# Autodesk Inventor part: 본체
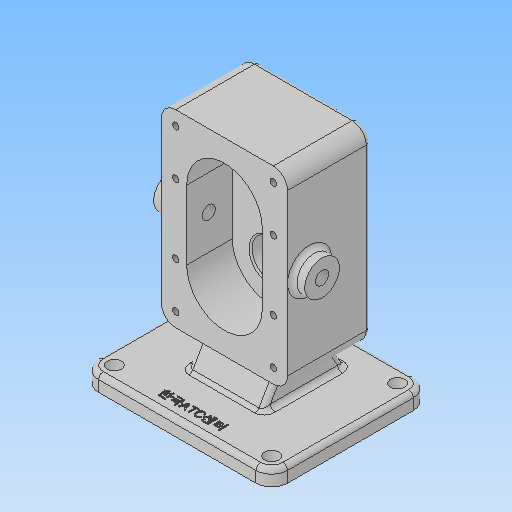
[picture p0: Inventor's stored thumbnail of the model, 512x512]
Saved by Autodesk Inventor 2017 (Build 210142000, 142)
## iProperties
Part Number: 본체
Material: 일반
Document SubType Name: Modeling
Designer: MRC
Density: 1 g/cm^3
Appearance: 기본값
Mass: 546.121 g
Surface Area: 823.386 cm^2
Volume: 546.121 cm^3
Author: MRC
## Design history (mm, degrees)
sketch "스케치1"
  geometry: L1 (40, -60)-(-40, -60); L2 (-40, -60)-(-40, 60); L3 (-40, 60)-(40, 60); L4 (40, 60)-(40, -60); L5 (40, -60)-(-40, 60); L6 (-40, -60)-(40, 60); 1 further point
  constraints: 12 end point, 2 midpoint, 2 parallel, 1 horizontal, 1 perpendicular
  dimensions: "d0" = 80 distance of L2.end L3.end; "d1" = 120 distance of L3.end L1.start
extrude "돌출1" new body sketch "스케치1" distance "d2" = 14; taper "d3" = 0 deg; dims "d5" = 39, "d6" = 0
fillet "모깎기1" dims "d4" = 9
sketch "스케치2"
  geometry: L1 (0, -49.175)-(0, 49.175); L2 (0, 22)-(0, -22); L3 (24, 22)-(24, -22); L4 (-24, -22)-(-24, 22); A1 r 24 centre (0, 22) between (24, 22) and (-24, 22); A2 r 24 centre (0, -22) between (-24, -22) and (24, -22); 2 further points
  constraints: 12 end point, 4 point on circle, 4 tangent, 2 centre point, 2 midpoint, 2 point on line, 1 coincident, 1 parallel, 1 vertical
  dimensions: "d12" = 22 distance of L2.start point (0, 0); "d13" = 24 radius of A1
extrude "돌출2" cut sketch "스케치2" distance "d14" = 29; taper "d15" = 0 deg
sketch "스케치3"
  geometry: C1 r 12.5 at (0, 22); C2 r 12.5 at (0, -22); A1 r 24 centre (0, 22) between (24, 22) and (-24, 22) reference; A2 r 24 centre (0, -22) between (-24, -22) and (24, -22) reference; 1 further point
  constraints: 2 centre point, 2 coincident
  dimensions: "d16" = 25 diameter of C1; "d17" = 25 diameter of C2
extrude "돌출3" cut sketch "스케치3" distance "d18" = 15; taper "d19" = 0 deg
chamfer "모따기1" distance "d20" = 1; stored, may be unused: second distance "d21" = 2, angle "d22" = 45 deg
sketch "스케치4"
  geometry: C1 r 19 at (0, 22); 1 further point
  constraints: 1 centre point, 1 vertical alignment
  dimensions: "d23" = 38 diameter of C1; "d24" = 22 distance of point (0, 0) C1.centre
extrude "돌출4" join sketch "스케치4" distance "d25" = 17; taper "d26" = 0 deg
sketch "스케치5"
  geometry: C1 r 19 at (0, 0) reference; C2 r 14 at (0, 0); 1 further point
  constraints: 1 centre point, 1 coincident
  dimensions: "d27" = 28 diameter of C2
extrude "돌출5" cut sketch "스케치5" distance "d28" = 7.3; taper "d29" = 0 deg
sketch "스케치6"
  geometry: C1 r 14 at (0, 0) reference; C2 r 8.5 at (0, 0); 1 further point
  constraints: 1 centre point, 1 coincident
  dimensions: "d30" = 17 diameter of C2
extrude "돌출6" cut sketch "스케치6" stored distance "d31" = 7.3; taper "d32" = 0 deg
fillet "모깎기2" dims "d33" = 0.5
sketch "스케치7"
  geometry: L1 (-80, 44)-(-90, 44); L2 (-90, 44)-(-90, -56); L3 (-90, -56)-(-80, -56); L4 (-80, -56)-(-80, 44); L5 (35.5, -15)-(46, -15) reference; L6 (46, -15)-(46, 14) reference; L7 (46, 14)-(60, 14) reference; L8 (60, 14)-(60, -39) reference; L9 (60, -39)-(41, -39) reference; L10 (41, -39)-(41, -56) reference; L11 (41, -56)-(36, -56) reference; L12 (36, -56)-(36, -49.2) reference; L13 (35.5, -48.7)-(30.5, -48.7) reference; L14 (30.5, -48.7)-(30.5, -30) reference; L15 (30.5, -30)-(34.5, -30) reference; L16 (34.5, -30)-(34.5, -16) reference; L17 (34.5, -16)-(35.5, -15) reference; L18 (-60, -39)-(-60, 14) reference; L19 (-60, 14)-(-46, 14) reference; L20 (-46, 14)-(-46, -15) reference; L21 (-46, -15)-(-35.5, -15) reference; L22 (-35.5, -15)-(-34.5, -16) reference; L23 (-34.5, -16)-(-34.5, -30) reference; L24 (-34.5, -30)-(-9.5, -30) reference; L25 (-9.5, -30)-(-9.5, -16) reference; L26 (-9.5, -16)-(-8.5, -15) reference; L27 (-8.5, -15)-(8.5, -15) reference; L28 (8.5, -15)-(9.5, -16) reference; L29 (9.5, -16)-(9.5, -30) reference; L30 (9.5, -30)-(13.5, -30) reference; L31 (13.5, -30)-(13.5, -48.7) reference; L32 (13.5, -48.7)-(8.5, -48.7) reference; L33 (8, -49.2)-(8, -56) reference; L34 (8, -56)-(3, -56) reference; L35 (3, -56)-(3, -39) reference; L36 (3, -39)-(-60, -39) reference; A1 r 0.5 centre (35.5, -49.2) between (36, -49.2) and (35.5, -48.7) reference; A2 r 0.5 centre (8.5, -49.2) between (8.5, -48.7) and (8, -49.2) reference; 1 further point
  constraints: 8 end point, 2 parallel, 1 collinear, 1 horizontal, 1 perpendicular
  dimensions: "d37" = 100 distance of L3.end L1.start; "d38" = 10 distance of L2.end L3.end; "d39" = 80 distance from line of L4 point (0, 0)
extrude "돌출7" join sketch "스케치7" stored distance "d40" = 120; taper "d41" = 0 deg
fillet "모깎기3" dims "d42" = 10
fillet "모깎기4" dims "d43" = 3
sketch "스케치8"
  geometry: L1 (-53, 0)-(-53, 102) reference; C1 r 11 at (-39, 51); 1 further point
  constraints: 1 centre point, 1 coincident
  dimensions: "d44" = 22 diameter of C1; "d45" = 14 distance from line of C1.centre L1
extrude "돌출8" join sketch "스케치8" distance "d46" = 8; taper "d47" = 0 deg
sketch "스케치10"
  geometry: C1 r 4.5 at (100, 7); C2 r 4.5 at (0, 7); C3 r 4.5 at (0, 87); C4 r 4.5 at (100, 87); A1 r 7 centre (0, 7) between (-7, 7) and (0, 0) reference; A2 r 7 centre (100, 7) between (100, 0) and (107, 7) reference; A3 r 7 centre (100, 87) between (107, 87) and (100, 94) reference; A4 r 7 centre (0, 87) between (0, 94) and (-7, 87) reference; 1 further point
  constraints: 4 centre point, 4 coincident
  dimensions: "d59" = 9 diameter of C1; "d60" = 9 diameter of C2; "d61" = 9 diameter of C3; "d62" = 9 diameter of C4
extrude "돌출9" cut sketch "스케치10" distance "d63" = 10; taper "d64" = 0 deg
sketch "스케치11"
  geometry: A1 r 9 centre (31, 51) between (40, 51) and (31, 60) reference; A2 r 9 centre (-31, 51) between (-31, 60) and (-40, 51) reference; 5 further points
  constraints: 4 vertical alignment
  dimensions: "d65" = 29 distance of point (-31, 22) A2.centre; "d66" = 44 distance of point (-31, -22) point (-31, 22); "d67" = 29 distance of point (31, 22) A1.centre; "d68" = 44 distance of point (31, -22) point (31, 22)
hole "구멍2" sketch "스케치11" at (-31, 22), (31, 22), (31, -22), (-31, -22) diameter "d69" = 4.134; stored, may be unused: countersink angle "d73" = 90 deg, drill point angle "d75" = 118 deg; dims "d70" = 10, "d71" = 4, "d72" = 2, "d74" = 12
hole "구멍3" diameter "d78" = 4.134; stored, may be unused: countersink angle "d82" = 90 deg, drill point angle "d84" = 118 deg; dims "d76" = 10, "d77" = 10, "d79" = 10, "d80" = 4, "d81" = 2, "d83" = 12
sketch "스케치15"
  geometry: L1 (-80, -39)-(-60, -27.453); L2 (-80, 14)-(-60, 2.453); L3 (-80, 34)-(-80, -46) reference; L4 (-60, -39)-(-60, 14) reference; L5 (-83, -56)-(-90, -56) reference; 1 further point
  constraints: 4 end point, 4 point on line
  dimensions: "d89" = 17 distance from line of L1.start L5; "d90" = 53 distance of L2.start L1.start; "d91" = 60 deg angle of L3 L1; "d92" = 60 deg angle of L3 L2
extrude "돌출10" join sketch "스케치15" stored distance "d93" = 48; taper "d94" = 0 deg
sketch "스케치16"
  geometry: L1 (-10, 87)-(-10, 7) reference; L2 (0, -3)-(100, -3) reference; 2 further points
  constraints: 1 other
  dimensions: "d95" = 60 distance from line of point (50, 7) L1; "d96" = 10 distance from line of L2 point (50, 7)
feature "엠보싱1" sketch "스케치16" dims "d0" = 80, "d1" = 120, "d13" = 24, "d97" = 0.5, "d98" = 0
fillet "모깎기5" dims "d99" = 3
fillet "모깎기6" dims "d100" = 3
fillet "모깎기7" dims "d101" = 3
chamfer "모따기3" distance "d102" = 0.7; stored, may be unused: second distance "d103" = 2, angle "d104" = 30 deg
hole "구멍4" diameter "d107" = 8.376; stored, may be unused: countersink angle "d111" = 90 deg, drill point angle "d113" = 118 deg; dims "d108" = 20, "d109" = 4, "d110" = 2, "d112" = 30, "d114" = 10, "d115" = 10
fillet "모깎기8" dims "d116" = 3
node "솔리드1"
mirror "미러1"
mirror "미러2"
mirror "미러3"
mirror "미러4"
node "절단 모서리 투영1"
